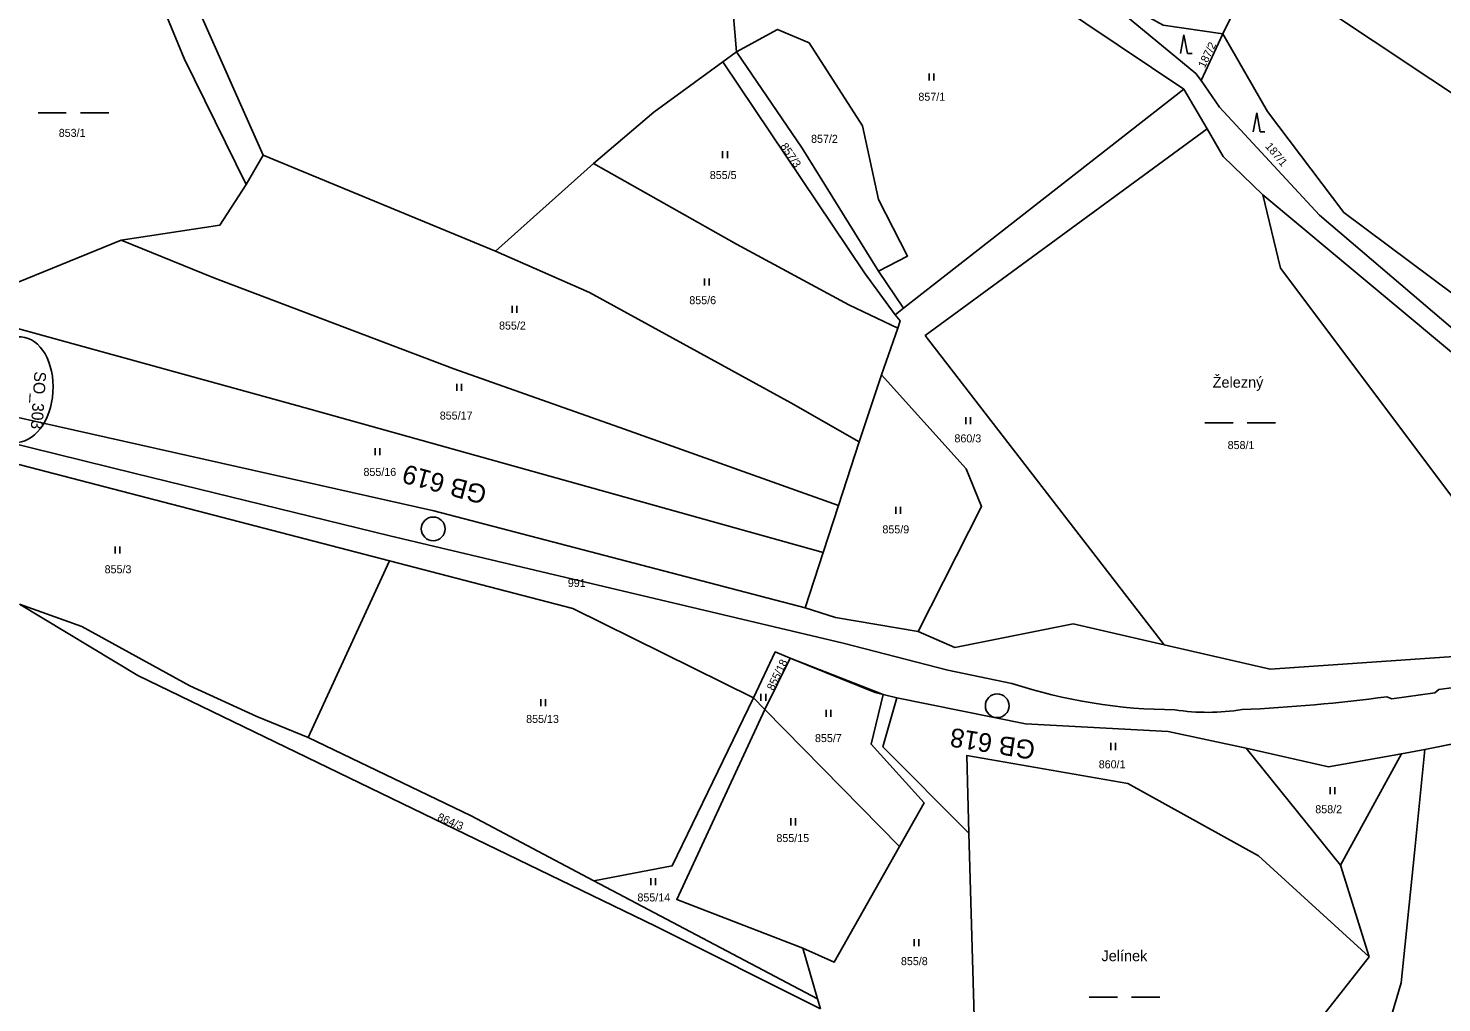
# Model space of a CAD drawing. Extents: x -7483133 to -743169, y -11317770 to -1127091.
# Drawn here: x -747508.3 to -747208.1, y -1131842.2 to -1131635.2 of the extents above; entities that cross this region are included whole.
import ezdxf

# ---------------------------------------------------------------- set-up
doc = ezdxf.new("R2010")
doc.units = 0
for name, color, linetype in [('_Násyp', 7, 'Continuous'), ('_Zabezpečovací zařízení_trasa', 7, 'Continuous'), ('bublina_fialová_čára_tučná', 7, 'Continuous'), ('Hranice parcel', 7, 'Continuous'), ('Parcelní čísla', 7, 'Continuous'), ('Pop  PČ popisy', 7, 'Continuous'), ('Vrstva 53', 7, 'Continuous'), ('Značky kultur', 7, 'Continuous'), ('ŽBP', 7, 'Continuous')]:
    doc.layers.add(name, color=color, linetype=linetype)

msp = doc.modelspace()

# ---------------------------------------------------------------- linework, layer by layer
at = {"layer": '_Zabezpečovací zařízení_trasa'}
for points in [[(-747299.39, -1131774.36), (-747312.96, -1131771.54), (-747335.19, -1131765.86), (-747431.5, -1131743.03), (-747485.59, -1131729.82), (-747529.87, -1131718.9), (-747616.75, -1131698.31), (-747822.02, -1131648.41), (-747861.48, -1131639.04), (-748013.3, -1131602), (-748116.9, -1131577.08), (-748210.22, -1131554.48), (-748277.3, -1131538.23)], [(-747208.72, -1131775.69), (-747209.57, -1131776.37), (-747218.69, -1131777.62), (-747219.71, -1131777.21)]]:
    msp.add_lwpolyline(points, dxfattribs=at)
for centre, radius, start, end in [((-748329.43, -1123662.93), 8189.81, 277.865136, 278.361097), ((-747264.33, -1131667.72), 112.26, 251.8015, 269.7738), ((-747265.34, -1131436.61), 343.64, 272.4776, 277.6319), ((-747257.75, -1131734.79), 45.73, 261.1687, 279.141)]:
    msp.add_arc(centre, radius, start, end, dxfattribs=at)
at = {"layer": 'bublina_fialová_čára_tučná'}
msp.add_ellipse((-747510.57, -1131712), major_axis=(0.72, 11.23), ratio=0.666667, dxfattribs=at)
at = {"layer": 'Hranice parcel'}
for p, q in [((-747361.08, -1131602.88), (-747357.88, -1131640.25)), ((-747478.47, -1131617.02), (-747458.45, -1131662.17)), ((-747254.6, -1131636.41), (-747247.17, -1131621.56)), ((-747254.6, -1131636.41), (-747259.18, -1131646.33)), ((-747357.88, -1131640.25), (-747360.8, -1131642.37)), ((-747322.41, -1131694.68), (-747262.86, -1131648.18)), ((-747257.91, -1131656.57), (-747262.86, -1131648.18)), ((-747458.45, -1131662.17), (-747462.01, -1131668.39)), ((-747409.06, -1131682.61), (-747458.45, -1131662.17)), ((-747388.27, -1131663.97), (-747409.06, -1131682.61)), ((-747327.68, -1131686.79), (-747322.41, -1131694.68)), ((-747324.17, -1131696.09), (-747322.41, -1131694.68)), ((-747327.11, -1131708.86), (-747323.64, -1131698.92)), ((-747331.81, -1131723.04), (-747327.11, -1131708.86)), ((-747336.24, -1131736.62), (-747331.81, -1131723.04)), ((-747336.24, -1131736.62), (-747339.49, -1131746.59)), ((-747448.86, -1131785.87), (-747431.62, -1131748.34)), ((-747339.49, -1131746.59), (-747343.31, -1131758.31)), ((-747346.48, -1131768.98), (-747351.83, -1131779.93)), ((-747351.83, -1131779.93), (-747354.27, -1131777.45)), ((-747323.8, -1131777.42), (-747326.7, -1131776.72)), ((-747351.83, -1131779.93), (-747323.26, -1131809)), ((-747211.65, -1131788.43), (-747166.79, -1131779.35)), ((-747249.62, -1131788.14), (-747229.61, -1131813)), ((-747229.61, -1131813), (-747216.62, -1131789.31)), ((-747211.65, -1131788.43), (-747216.62, -1131789.31)), ((-747223.51, -1131832.44), (-747229.61, -1131813)), ((-747340.66, -1131841.38), (-747388.18, -1131816.27)), ((-747343.77, -1131830.6), (-747340.66, -1131841.38)), ((-747223.51, -1131832.44), (-747265.2, -1131885.54)), ((-747340.66, -1131841.38), (-747340.05, -1131843.48))]:
    msp.add_line(p, q, dxfattribs=at)
for points in [[(-747462.01, -1131668.39), (-747475.19, -1131641.65), (-747484.66, -1131618.77), (-747495.81, -1131591.02)], [(-747262.86, -1131648.18), (-747290.52, -1131629.64), (-747320.83, -1131612.14), (-747361.08, -1131602.88)], [(-747129.15, -1131700.25), (-747185.86, -1131662.35), (-747247.17, -1131621.56)], [(-747283.76, -1131625.43), (-747267.27, -1131634.55), (-747254.6, -1131636.41)], [(-747259.18, -1131646.33), (-747260.33, -1131644.82), (-747283.76, -1131625.43)], [(-747357.88, -1131640.25), (-747349.2, -1131635.5), (-747342.45, -1131638.32), (-747331.11, -1131655.97), (-747327.7, -1131671.61), (-747321.53, -1131683.62), (-747327.68, -1131686.79)], [(-747172.52, -1131716.41), (-747228.87, -1131674.36), (-747245.07, -1131652.89), (-747254.6, -1131636.41)], [(-747357.88, -1131640.25), (-747343.93, -1131660.68), (-747327.68, -1131686.79)], [(-747360.8, -1131642.37), (-747375.43, -1131653.05), (-747388.27, -1131663.97)], [(-747324.17, -1131696.09), (-747330.67, -1131687.18), (-747360.8, -1131642.37)], [(-747259.18, -1131646.33), (-747255.29, -1131651.97), (-747234.06, -1131674.93), (-747201.42, -1131702.74), (-747172.52, -1131716.41)], [(-747257.91, -1131656.57), (-747317.79, -1131700.5), (-747267.01, -1131766.16)], [(-747246.06, -1131670.63), (-747254.48, -1131662.48), (-747257.91, -1131656.57)], [(-747388.27, -1131663.97), (-747357.85, -1131681.06), (-747334, -1131693.97), (-747323.64, -1131698.92)], [(-747488.58, -1131680.22), (-747467.61, -1131677.03), (-747462.01, -1131668.39)], [(-747194.42, -1131749.94), (-747242.32, -1131686.21), (-747246.06, -1131670.63)], [(-747143.51, -1131733.86), (-747163.2, -1131726.49), (-747177.09, -1131722.8), (-747200.93, -1131708.24), (-747246.06, -1131670.63)], [(-747528.4, -1131694.14), (-747525.49, -1131687.82), (-747512.4, -1131689.95), (-747488.58, -1131680.22)], [(-747488.58, -1131680.22), (-747468.94, -1131688.21), (-747417.95, -1131707.56), (-747381.64, -1131720.38), (-747336.24, -1131736.62)], [(-747331.81, -1131723.04), (-747346.34, -1131714.79), (-747389.09, -1131691.38), (-747409.06, -1131682.61)], [(-747339.49, -1131746.59), (-747451.3, -1131715.37), (-747528.4, -1131694.14)], [(-747323.64, -1131698.92), (-747323.11, -1131697.35), (-747324.17, -1131696.09)], [(-747343.31, -1131758.31), (-747422.18, -1131737.69), (-747515.95, -1131716.72), (-747542.02, -1131707.68)], [(-747319.28, -1131763.36), (-747305.82, -1131736.8), (-747309.11, -1131728.78), (-747327.11, -1131708.86)], [(-747431.62, -1131748.34), (-747522.4, -1131724.74), (-747551.8, -1131720.33)], [(-747431.62, -1131748.34), (-747392.64, -1131758.47), (-747354.27, -1131777.45)], [(-747510.21, -1131757.54), (-747496.95, -1131762.32), (-747474.01, -1131774.9), (-747459.79, -1131781.43), (-747448.86, -1131785.87)], [(-747340.05, -1131843.48), (-747375.12, -1131825.91), (-747485.07, -1131772.73), (-747510.21, -1131757.54)], [(-747343.31, -1131758.31), (-747336.85, -1131760.37), (-747319.28, -1131763.36)], [(-747319.28, -1131763.36), (-747311.5, -1131766.78), (-747286.37, -1131761.74), (-747267.01, -1131766.16)], [(-747267.01, -1131766.16), (-747244.55, -1131771.35), (-747202.38, -1131768.48)], [(-747354.27, -1131777.45), (-747349.64, -1131767.7), (-747346.48, -1131768.98)], [(-747326.7, -1131776.72), (-747328.4, -1131776.31), (-747346.48, -1131768.98)], [(-747388.18, -1131816.27), (-747371.51, -1131813.1), (-747354.27, -1131777.45)], [(-747323.26, -1131809), (-747318.03, -1131799.74), (-747329.29, -1131787.29), (-747326.7, -1131776.72)], [(-747308.51, -1131806.18), (-747326.78, -1131787.84), (-747323.8, -1131777.42)], [(-747249.62, -1131788.14), (-747266.19, -1131784.57), (-747296.48, -1131782.93), (-747323.8, -1131777.42)], [(-747343.77, -1131830.6), (-747370.56, -1131820.28), (-747351.83, -1131779.93)], [(-747388.18, -1131816.27), (-747414.25, -1131802.49), (-747448.86, -1131785.87)], [(-747308.51, -1131806.18), (-747308.97, -1131789.7), (-747274.72, -1131795.65), (-747246.96, -1131810.99), (-747223.51, -1131832.44)], [(-747216.62, -1131789.31), (-747232.12, -1131792.08), (-747249.62, -1131788.14)], [(-747224.99, -1131886.58), (-747230.08, -1131883.19), (-747216.68, -1131837.99), (-747213.89, -1131810.39), (-747211.65, -1131788.43)], [(-747332.1, -1131862.53), (-747307.27, -1131850), (-747308.51, -1131806.18)], [(-747323.26, -1131809), (-747337.16, -1131833.58), (-747343.77, -1131830.6)]]:
    msp.add_lwpolyline(points, dxfattribs=at)
at = {"layer": 'Vrstva 53'}
for points in [[(-747515.95, -1131716.72), (-747422.18, -1131737.69), (-747343.31, -1131758.31), (-747336.85, -1131760.37), (-747319.28, -1131763.36), (-747311.5, -1131766.78), (-747286.37, -1131761.74), (-747267.01, -1131766.16), (-747244.55, -1131771.35), (-747202.38, -1131768.48), (-747143.72, -1131765.05), (-747130.74, -1131762.5), (-747114.55, -1131760.12), (-747084.49, -1131755.95), (-747066.3, -1131762.59)], [(-747066.3, -1131762.59), (-747075.87, -1131764.45), (-747113.75, -1131771.83), (-747127.4, -1131774.15), (-747162.4, -1131778.78), (-747166.79, -1131779.35), (-747211.65, -1131788.43), (-747216.62, -1131789.31), (-747232.12, -1131792.08), (-747249.62, -1131788.14), (-747266.19, -1131784.57), (-747296.48, -1131782.93), (-747323.8, -1131777.42), (-747326.7, -1131776.72), (-747346.48, -1131768.98), (-747349.64, -1131767.7), (-747354.27, -1131777.45), (-747392.64, -1131758.47), (-747431.62, -1131748.34), (-747522.4, -1131724.74)]]:
    msp.add_lwpolyline(points, dxfattribs=at)
at = {"layer": 'Značky kultur'}
for p, q in [((-747262.84, -1131636.62), (-747263.59, -1131640.62)), ((-747262.09, -1131640.62), (-747262.84, -1131636.62)), ((-747262.09, -1131640.62), (-747261.09, -1131640.62)), ((-747316.93, -1131646.32), (-747316.93, -1131644.82)), ((-747315.93, -1131646.32), (-747315.93, -1131644.82)), ((-747506.24, -1131653.22), (-747500.24, -1131653.22)), ((-747497.24, -1131653.22), (-747491.24, -1131653.22)), ((-747247.38, -1131653.21), (-747248.13, -1131657.21)), ((-747246.63, -1131657.21), (-747247.38, -1131653.21)), ((-747246.63, -1131657.21), (-747245.63, -1131657.21)), ((-747360.82, -1131662.85), (-747360.82, -1131661.35)), ((-747359.82, -1131662.85), (-747359.82, -1131661.35)), ((-747364.68, -1131689.9), (-747364.68, -1131688.4)), ((-747363.68, -1131689.9), (-747363.68, -1131688.4)), ((-747405.53, -1131695.68), (-747405.53, -1131694.18)), ((-747404.53, -1131695.68), (-747404.53, -1131694.18)), ((-747417.29, -1131712.27), (-747417.29, -1131710.77)), ((-747416.29, -1131712.27), (-747416.29, -1131710.77)), ((-747309.19, -1131719.3), (-747309.19, -1131717.8)), ((-747308.19, -1131719.3), (-747308.19, -1131717.8)), ((-747258.39, -1131719.04), (-747252.39, -1131719.04)), ((-747249.39, -1131719.04), (-747243.39, -1131719.04)), ((-747434.67, -1131725.89), (-747434.67, -1131724.39)), ((-747433.67, -1131725.89), (-747433.67, -1131724.39)), ((-747324.01, -1131738.34), (-747324.01, -1131736.84)), ((-747323.01, -1131738.34), (-747323.01, -1131736.84)), ((-747489.85, -1131746.77), (-747489.85, -1131745.27)), ((-747488.85, -1131746.77), (-747488.85, -1131745.27)), ((-747399.46, -1131779.22), (-747399.46, -1131777.72)), ((-747398.46, -1131779.22), (-747398.46, -1131777.72)), ((-747352.68, -1131778.11), (-747352.68, -1131776.61)), ((-747351.68, -1131778.11), (-747351.68, -1131776.61)), ((-747338.81, -1131781.46), (-747338.81, -1131779.96)), ((-747337.81, -1131781.46), (-747337.81, -1131779.96)), ((-747278.38, -1131788.52), (-747278.38, -1131787.02)), ((-747277.38, -1131788.52), (-747277.38, -1131787.02)), ((-747231.75, -1131797.89), (-747231.75, -1131796.39)), ((-747230.75, -1131797.89), (-747230.75, -1131796.39)), ((-747346.33, -1131804.52), (-747346.33, -1131803.02)), ((-747345.33, -1131804.52), (-747345.33, -1131803.02)), ((-747376.07, -1131817.22), (-747376.07, -1131815.72)), ((-747375.07, -1131817.22), (-747375.07, -1131815.72)), ((-747320.17, -1131830.16), (-747320.17, -1131828.66)), ((-747319.17, -1131830.16), (-747319.17, -1131828.66)), ((-747282.95, -1131841), (-747276.95, -1131841)), ((-747273.95, -1131841), (-747267.95, -1131841))]:
    msp.add_line(p, q, dxfattribs=at)
at = {"layer": 'ŽBP'}
for centre in [(-747422.31, -1131741.56), (-747302.5, -1131779.12)]:
    msp.add_circle(centre, 2.52, dxfattribs=at)

# ---------------------------------------------------------------- texts
at = {"layer": '_Násyp'}
msp.add_text('SO_303', height=2.5, rotation=266.3528, dxfattribs=at).set_placement((-747507.01, -1131708.06))
at = {"layer": 'Parcelní čísla'}
for s, rotation, p in [('187/2', 64, (-747258.41, -1131643.81)), ('857/3', 304, (-747348.63, -1131660.3)), ('187/1', 310, (-747245.66, -1131660.38)), ('855/18', 64, (-747350.01, -1131776.03)), ('864/3', 337, (-747421.57, -1131803.38))]:
    msp.add_text(s, height=1.7, rotation=rotation, dxfattribs=at).set_placement(p)
for s, p in [('857/1', (-747319.24, -1131650.63)), ('853/1', (-747501.85, -1131658.3)), ('857/2', (-747342.04, -1131659.57)), ('855/5', (-747363.55, -1131667.26)), ('855/6', (-747367.9, -1131693.84)), ('855/2', (-747408.32, -1131699.23)), ('855/17', (-747420.91, -1131718.34)), ('860/3', (-747311.58, -1131723.19)), ('858/1', (-747253.55, -1131724.61)), ('855/16', (-747437.12, -1131730.31)), ('855/9', (-747326.88, -1131742.51)), ('855/3', (-747492.1, -1131750.98)), ('991', (-747393.71, -1131753.89)), ('855/13', (-747402.56, -1131782.77)), ('855/7', (-747341.21, -1131786.84)), ('860/1', (-747280.93, -1131792.4)), ('858/2', (-747234.93, -1131801.95)), ('855/15', (-747349.4, -1131808.07)), ('855/14', (-747378.92, -1131820.68)), ('855/8', (-747322.95, -1131834.21))]:
    msp.add_text(s, height=1.7, dxfattribs=at).set_placement(p)
at = {"layer": 'Pop  PČ popisy'}
for s, p in [('Železný ', (-747256.73, -1131711.57)), ('Jelínek', (-747280.35, -1131833.37))]:
    msp.add_text(s, height=2.3, dxfattribs=at).set_placement(p)
at = {"layer": 'ŽBP'}
for s, rotation, p in [('GB 619', 164.7872, (-747410.63, -1131732.56)), ('GB 618', 170.907, (-747294.21, -1131786.66))]:
    msp.add_text(s, height=4, rotation=rotation, dxfattribs=at).set_placement(p)

doc.saveas('drawing.dxf')
